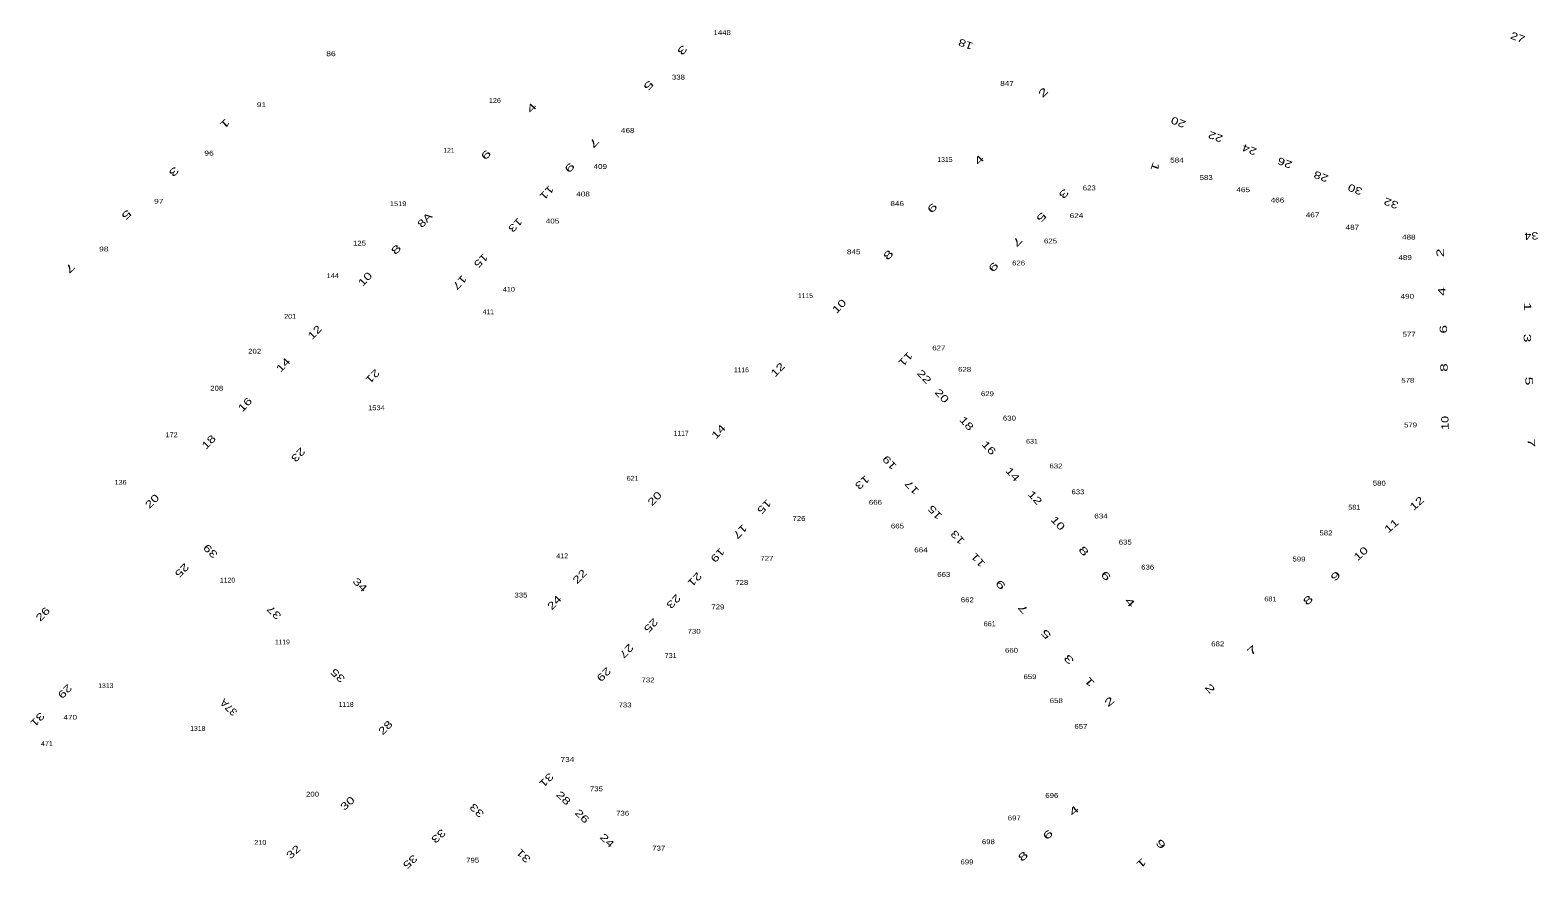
# Model space of a CAD drawing. Extents: x -828673 to -815583, y -1077737 to -1063807.
# Drawn here: x -819548.1 to -819237.8, y -1069113.6 to -1068941 of the extents above; entities that cross this region are included whole.
import ezdxf
from ezdxf.enums import TextEntityAlignment as Align

# ---------------------------------------------------------------- set-up
doc = ezdxf.new("R2010")
doc.units = 0
doc.header["$LTSCALE"] = 0.4
doc.layers.add('1', color=7, linetype='Continuous')
doc.layers.add('2', color=7, linetype='Continuous')

msp = doc.modelspace()

# ---------------------------------------------------------------- texts
at = {"layer": '1'}
for s, width, p in [('1448', 1.2, (-819405.677, -1068941.98)), ('86', 1.3, (-819486.171, -1068946.327)), ('338', 1.2, (-819414.676, -1068951.136)), ('847', 1.25, (-819347.062, -1068952.43)), ('91', 1.3, (-819500.461, -1068956.814)), ('126', 1.1, (-819452.434, -1068955.932)), ('468', 1.25, (-819425.104, -1068962.104)), ('96', 1.3, (-819511.261, -1068966.78)), ('409', 1.25, (-819430.75, -1068969.532)), ('1315', 1.05, (-819359.837, -1068968.094)), ('584', 1.25, (-819312.093, -1068968.217)), ('583', 1.2, (-819306.091, -1068971.794)), ('97', 1.3, (-819521.602, -1068976.704)), ('408', 1.25, (-819434.299, -1068975.188)), ('623', 1.2, (-819330.15, -1068973.939)), ('465', 1.25, (-819298.465, -1068974.309)), ('466', 1.25, (-819291.414, -1068976.442)), ('1519', 1.15, (-819472.344, -1068977.171)), ('846', 1.25, (-819369.661, -1068977.162)), ('624', 1.25, (-819332.774, -1068979.649)), ('467', 1.25, (-819284.198, -1068979.493)), ('405', 1.25, (-819440.581, -1068980.751)), ('487', 1.25, (-819275.999, -1068982.02)), ('125', 1.2, (-819480.311, -1068985.321)), ('625', 1.2, (-819338.12, -1068984.867)), ('488', 1.25, (-819264.392, -1068984.056)), ('98', 1.3, (-819532.9, -1068986.516)), ('845', 1.25, (-819378.612, -1068987.093)), ('489', 1.25, (-819265.155, -1068988.27)), ('144', 1.15, (-819485.806, -1068992.009)), ('626', 1.2, (-819344.679, -1068989.395)), ('410', 1.1, (-819449.554, -1068994.81)), ('490', 1.25, (-819264.696, -1068996.244)), ('201', 1.1, (-819494.571, -1069000.381)), ('577', 1.2, (-819264.335, -1069004.061)), ('202', 1.2, (-819501.872, -1069007.56)), ('627', 1.2, (-819361.098, -1069006.887)), ('628', 1.2, (-819355.785, -1069011.284)), ('578', 1.2, (-819264.597, -1069013.544)), ('208', 1.2, (-819509.681, -1069015.161)), ('629', 1.2, (-819351.095, -1069016.304)), ('1534', 1.15, (-819476.81, -1069019.2)), ('630', 1.2, (-819346.569, -1069021.325)), ('579', 1.2, (-819264.039, -1069022.732)), ('172', 1.1, (-819518.966, -1069024.747)), ('631', 1.1, (-819341.921, -1069026.091)), ('632', 1.2, (-819337.001, -1069031.177)), ('136', 1.1, (-819529.456, -1069034.545)), ('621', 1.1, (-819424.098, -1069033.705)), ('580', 1.2, (-819270.46, -1069034.709)), ('666', 1.2, (-819374.141, -1069038.643)), ('633', 1.2, (-819332.475, -1069036.493)), ('634', 1.25, (-819327.72, -1069041.481)), ('581', 1.1, (-819275.609, -1069039.664)), ('726', 1.2, (-819389.876, -1069041.983)), ('665', 1.2, (-819369.608, -1069043.532)), ('582', 1.2, (-819281.446, -1069044.948)), ('635', 1.2, (-819322.742, -1069046.845)), ('412', 1.1, (-819438.596, -1069049.678)), ('727', 1.2, (-819396.47, -1069050.179)), ('664', 1.25, (-819364.765, -1069048.446)), ('599', 1.2, (-819286.989, -1069050.329)), ('663', 1.2, (-819360.073, -1069053.496)), ('636', 1.2, (-819318.118, -1069051.996)), ('1120', 1.05, (-819507.445, -1069054.669)), ('728', 1.2, (-819401.644, -1069055.153)), ('335', 1.2, (-819447.076, -1069057.755)), ('729', 1.2, (-819406.558, -1069060.184)), ('662', 1.2, (-819355.229, -1069058.723)), ('681', 1.1, (-819292.882, -1069058.544)), ('730', 1.2, (-819411.453, -1069065.209)), ('661', 1.1, (-819350.623, -1069063.659)), ('660', 1.2, (-819346.134, -1069069.115)), ('682', 1.2, (-819303.705, -1069067.798)), ('731', 1.1, (-819416.272, -1069070.182)), ('732', 1.2, (-819420.937, -1069075.223)), ('659', 1.2, (-819342.329, -1069074.545)), ('1313', 1.05, (-819532.486, -1069076.391)), ('733', 1.2, (-819425.652, -1069080.365)), ('658', 1.2, (-819336.933, -1069079.476)), ('470', 1.25, (-819539.807, -1069082.902)), ('1318', 1.05, (-819513.57, -1069085.196)), ('657', 1.2, (-819331.861, -1069084.78)), ('471', 1.1, (-819544.613, -1069088.328)), ('734', 1.25, (-819437.514, -1069091.589)), ('735', 1.2, (-819431.554, -1069097.628)), ('200', 1.2, (-819489.961, -1069098.733)), ('696', 1.2, (-819337.847, -1069098.993)), ('736', 1.2, (-819426.152, -1069102.652)), ('697', 1.2, (-819345.573, -1069103.625)), ('210', 1.1, (-819500.706, -1069108.652)), ('737', 1.2, (-819418.728, -1069109.841)), ('698', 1.2, (-819350.9, -1069108.522)), ('795', 1.2, (-819457.015, -1069112.317)), ('699', 1.2, (-819355.307, -1069112.674))]:
    msp.add_text(s, height=1, dxfattribs=dict(at, width=width)).set_placement(p, align=Align.CENTER)
for s, p in [('121', (-819461.888, -1068966.194)), ('1115', (-819388.525, -1068996.117)), ('411', (-819453.794, -1068999.429)), ('1116', (-819401.717, -1069011.39)), ('1117', (-819414.11, -1069024.403)), ('1119', (-819496.165, -1069067.403)), ('1118', (-819483.043, -1069080.264))]:
    msp.add_text(s, height=1, dxfattribs=at).set_placement(p, align=Align.CENTER)
at = {"layer": '2'}
for s, rotation, width, p in [('27', 339.783, 1.35, (-819242.2482, -1068943.162)), ('3', 226.147, 1.75, (-819414.4016, -1068944.5644)), ('18', 159.866, 1.35, (-819355.3203, -1068943.1641)), ('5', 226.275, 1.75, (-819421.3612, -1068951.8371)), ('2', 46.072, 1.75, (-819339.0878, -1068954.3068)), ('4', 46.085, 1.75, (-819444.37, -1068957.4777)), ('1', 222.843, 1.75, (-819508.4975, -1068959.6834)), ('20', 158.728, 1.35, (-819311.5674, -1068959.2225)), ('22', 159.233, 1.35, (-819303.8936, -1068962.2121)), ('6', 45.964, 1.75, (-819453.7377, -1068967.1503)), ('7', 226.673, 1.75, (-819432.6014, -1068963.6539)), ('24', 159.259, 1.35, (-819296.9259, -1068964.8597)), ('3', 222.953, 1.75, (-819518.9895, -1068969.562)), ('9', 225.981, 1.75, (-819437.5935, -1068968.7533)), ('4', 46.228, 1.75, (-819352.2726, -1068968.1798)), ('1', 250.303, 1.65, (-819317.2808, -1068968.8422)), ('26', 159.177, 1.35, (-819289.6449, -1068967.5818)), ('28', 159.426, 1.35, (-819282.2014, -1068970.4048)), ('30', 159.11, 1.35, (-819275.1716, -1068973.053)), ('11', 227.023, 1.4, (-819442.3098, -1068973.9112)), ('3', 226.245, 1.75, (-819335.9002, -1068974.1293)), ('32', 159.358, 1.35, (-819267.7606, -1068975.9092)), ('5', 222.688, 1.75, (-819528.739, -1068978.4282)), ('6', 46.464, 1.75, (-819361.9095, -1068978.0941)), ('5', 226.348, 1.75, (-819340.5252, -1068978.9548)), ('8A', 45.794, 1.35, (-819466.3151, -1068980.5754)), ('13', 226.012, 1.4, (-819448.7413, -1068980.5711)), ('7', 225.898, 1.75, (-819345.4803, -1068983.973)), ('34', 182.252, 1.3, (-819239.206, -1068982.5962)), ('8', 45.789, 1.75, (-819472.2396, -1068986.6295)), ('15', 225.834, 1.4, (-819455.8324, -1068987.9044)), ('8', 46.252, 1.75, (-819370.9544, -1068987.7431)), ('2', 91.381, 1.6, (-819257.1949, -1068986.7681)), ('7', 223.57, 1.75, (-819540.3711, -1068989.4305)), ('10', 46.589, 1.4, (-819478.6128, -1068992.7279)), ('9', 226.212, 1.75, (-819350.3977, -1068989.192)), ('17', 226.185, 1.4, (-819460.2258, -1068992.3993)), ('4', 91.985, 1.6, (-819256.8715, -1068994.7415)), ('10', 46.367, 1.4, (-819381.0584, -1068998.306)), ('1', 271.366, 1.6, (-819240.7093, -1068997.8916)), ('12', 46.062, 1.4, (-819488.9776, -1069003.6799)), ('6', 91.184, 1.6, (-819256.5378, -1069002.5275)), ('3', 271.469, 1.6, (-819240.7457, -1069004.3638)), ('14', 45.999, 1.4, (-819495.4723, -1069010.39)), ('12', 46.221, 1.4, (-819393.7147, -1069011.3799)), ('11', 226.5, 1.4, (-819368.4612, -1069008.1797)), ('8', 91.23, 1.6, (-819256.4075, -1069010.4036)), ('21', 226.192, 1.4, (-819478.1156, -1069011.6933)), ('22', 312.752, 1.4, (-819364.6501, -1069012.8009)), ('5', 271.536, 1.6, (-819240.3997, -1069013.2199)), ('20', 312.466, 1.4, (-819361.0123, -1069016.7386)), ('16', 46.157, 1.4, (-819503.3234, -1069018.54)), ('14', 46.244, 1.4, (-819405.8874, -1069024.1407)), ('18', 312.51, 1.4, (-819355.9205, -1069022.4057)), ('10', 91.197, 1.3, (-819256.2109, -1069021.7997)), ('18', 46.06, 1.4, (-819510.7946, -1069026.2689)), ('7', 272.012, 1.6, (-819239.9101, -1069025.9357)), ('23', 226.192, 1.4, (-819493.4426, -1069027.8633)), ('16', 312.466, 1.4, (-819351.3373, -1069027.4346)), ('19', 132.653, 1.4, (-819370.702, -1069029.4902)), ('14', 312.418, 1.4, (-819346.4512, -1069032.8826)), ('13', 221.797, 1.4, (-819377.3331, -1069033.5198)), ('17', 132.487, 1.4, (-819366.0943, -1069034.5796)), ('20', 45.802, 1.4, (-819522.4331, -1069038.4494)), ('20', 46.364, 1.4, (-819419.0373, -1069037.9011)), ('15', 226.336, 1.4, (-819397.5545, -1069038.5457)), ('12', 312.496, 1.4, (-819341.8599, -1069037.7058)), ('12', 41.971, 1.4, (-819262.2596, -1069038.9193)), ('15', 132.408, 1.4, (-819361.3505, -1069039.7293)), ('17', 226.005, 1.4, (-819402.5045, -1069043.6701)), ('13', 132.402, 1.4, (-819356.6834, -1069044.8812)), ('10', 312.51, 1.4, (-819337.1365, -1069042.9557)), ('11', 41.615, 1.4, (-819267.4791, -1069043.5434)), ('39', 135.729, 1.4, (-819510.4505, -1069047.6875)), ('19', 226.687, 1.4, (-819407.1389, -1069048.5205)), ('11', 132.365, 1.4, (-819352.4928, -1069049.5654)), ('8', 312.656, 1.75, (-819331.8243, -1069048.6793)), ('10', 41.943, 1.4, (-819273.7698, -1069049.2556)), ('25', 225.506, 1.4, (-819517.3544, -1069051.6489)), ('22', 46.233, 1.4, (-819434.4451, -1069053.9368)), ('21', 226.34, 1.4, (-819411.8523, -1069053.5247)), ('6', 312.41, 1.75, (-819327.2678, -1069053.7997)), ('9', 41.242, 1.75, (-819278.9834, -1069053.9147)), ('34', 315.751, 1.4, (-819480.7043, -1069055.6528)), ('9', 132.402, 1.75, (-819347.8311, -1069054.6202)), ('24', 46.292, 1.4, (-819439.6583, -1069059.3097)), ('23', 226.165, 1.4, (-819416.1934, -1069058.0591)), ('4', 312.455, 1.75, (-819322.3147, -1069059.2157)), ('8', 42.004, 1.75, (-819284.6484, -1069058.8426)), ('26', 46.029, 1.4, (-819544.9192, -1069061.6877)), ('37', 135.75, 1.4, (-819497.3727, -1069060.3061)), ('25', 226.34, 1.4, (-819420.8583, -1069062.9817)), ('7', 132.207, 1.75, (-819343.1893, -1069059.6184)), ('5', 132.325, 1.75, (-819338.498, -1069064.7965)), ('27', 226.437, 1.4, (-819425.9056, -1069068.2616)), ('7', 41.96, 1.75, (-819296.161, -1069069.1782)), ('3', 132.594, 1.75, (-819333.7888, -1069070.0061)), ('35', 135.75, 1.4, (-819484.2497, -1069073.2811)), ('29', 225.16, 1.4, (-819430.55, -1069073.0621)), ('1', 132.308, 1.75, (-819329.5438, -1069074.6393)), ('29', 226.322, 1.4, (-819541.4369, -1069076.5525)), ('2', 312.481, 1.75, (-819305.8348, -1069076.984)), ('37A', 135.583, 1.1, (-819506.7221, -1069079.8369)), ('2', 41.902, 1.75, (-819325.5124, -1069079.735)), ('31', 226.137, 1.4, (-819547.0777, -1069082.3513)), ('28', 45.718, 1.4, (-819474.4412, -1069085.0656)), ('31', 225.837, 1.4, (-819442.3493, -1069094.8135)), ('30', 41.889, 1.4, (-819482.2718, -1069100.6667)), ('28', 315.746, 1.4, (-819438.8264, -1069099.556)), ('33', 135.765, 1.4, (-819455.6493, -1069101.0631)), ('26', 315.752, 1.4, (-819435.0223, -1069103.2858)), ('4', 41.355, 1.75, (-819332.816, -1069102.1747)), ('33', 222.205, 1.4, (-819464.5367, -1069106.3148)), ('6', 41.825, 1.75, (-819338.1606, -1069107.1071)), ('32', 42.334, 1.4, (-819493.3941, -1069110.677)), ('24', 315.75, 1.4, (-819429.8553, -1069108.2929)), ('6', 131.725, 1.75, (-819314.8655, -1069107.9997)), ('35', 222.177, 1.4, (-819470.3694, -1069111.5945)), ('31', 135.298, 1.4, (-819446.0509, -1069110.3945)), ('8', 41.987, 1.75, (-819343.2842, -1069111.5718)), ('1', 222, 1.75, (-819319.8927, -1069111.8994))]:
    msp.add_text(s, height=1.5, rotation=rotation, dxfattribs=dict(at, width=width)).set_placement(p, align=Align.CENTER)

doc.saveas('drawing.dxf')
